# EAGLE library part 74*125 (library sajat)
Quad bus BUFFER, 3-state
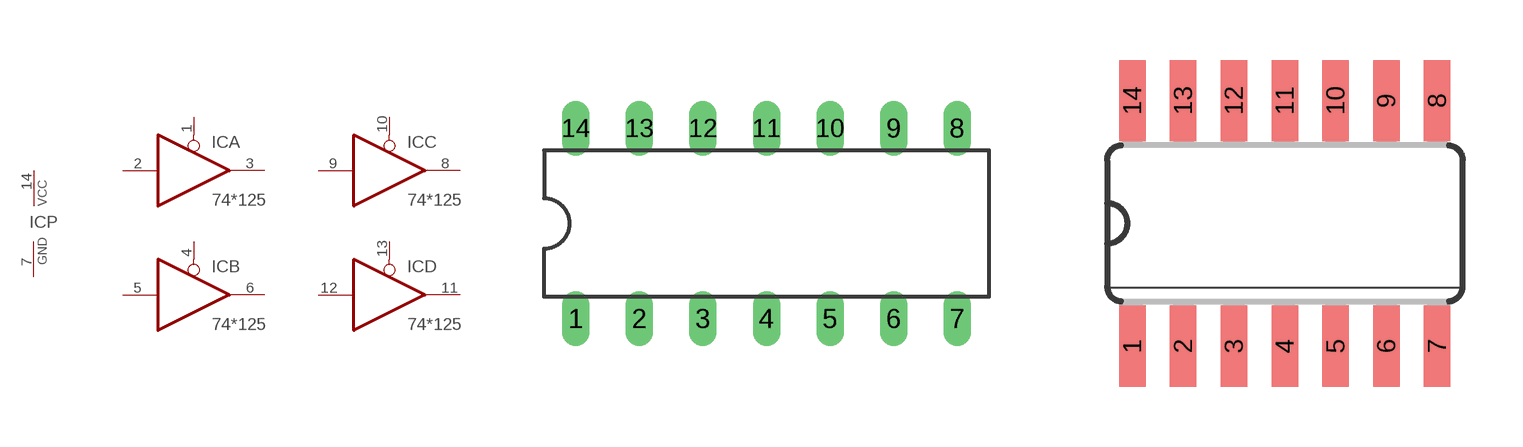
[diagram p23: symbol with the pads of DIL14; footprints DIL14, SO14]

Designator prefix IC; gates A=74125 B=74125 C=74125 D=74125 P=PWRN-1

## 74125N, 74AC125N, 74ACT125N, 74HC125N, 74HCT125N, 74LS125N  [DIL14]
1  A:OE  in
2  A:I  in
3  A:O  hiz
4  B:OE  in
5  B:I  in
6  B:O  hiz
7  P:GND  pwr
8  C:O  hiz
9  C:I  in
10  C:OE  in
11  D:O  hiz
12  D:I  in
13  D:OE  in
14  P:VCC  pwr

## 74AC125D, 74ACT125D, 74HC125D, 74HCT125D, 74LS125D  [SO14]
Pads as for DIL14

## Footprint DIL14 (pad centres in mm)
Dual In Line Package
drill 0.6 pad 1.016 long: 1 -7.62,-3.81; 2 -5.08,-3.81; 3 -2.54,-3.81; 4 0,-3.81; 5 2.54,-3.81; 6 5.08,-3.81; 7 7.62,-3.81; 8 7.62,3.81; 9 5.08,3.81; 10 2.54,3.81; 11 0,3.81; 12 -2.54,3.81; 13 -5.08,3.81; 14 -7.62,3.81

## Footprint SO14 (pad centres in mm)
Small Outline package 150 mil
smd 0.66 x 2.032: 1 -3.81,-3.073; 2 -2.54,-3.073; 3 -1.27,-3.073; 4 0,-3.073; 5 1.27,-3.073; 6 2.54,-3.073; 7 3.81,-3.073; 8 3.81,3.073; 9 2.54,3.073; 10 1.27,3.073; 11 0,3.073; 12 -1.27,3.073; 13 -2.54,3.073; 14 -3.81,3.073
